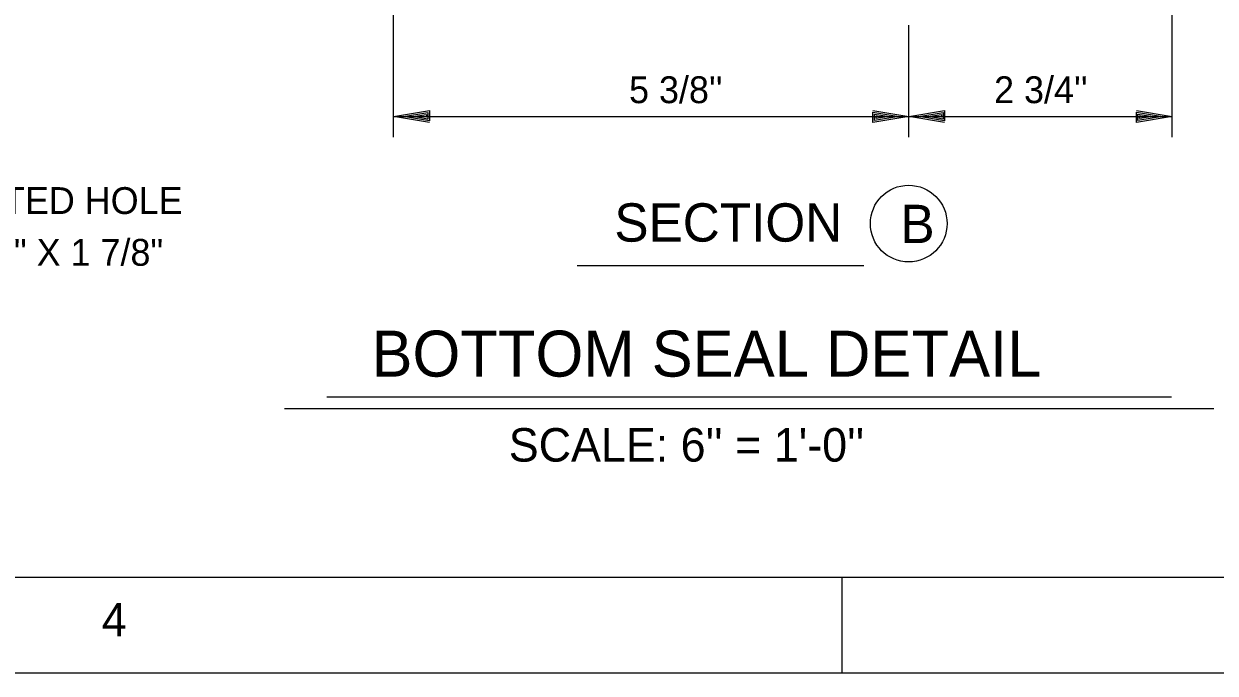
# Model space of a CAD drawing. Extents: x 0.1 to 13.5, y 0.1 to 9.5.
# Drawn here: x 4.244 to 6.316, y 0.125 to 1.255 of the extents above; entities that cross this region are included whole.
import ezdxf

# ---------------------------------------------------------------- set-up
doc = ezdxf.new("R2010")
doc.units = 0
for name, color, linetype in [('Level 1', 7, 'Continuous'), ('Level 25', 7, 'Continuous'), ('Level 3', 7, 'Continuous'), ('Level 50', 7, 'Continuous')]:
    doc.layers.add(name, color=color, linetype=linetype)

msp = doc.modelspace()

# ---------------------------------------------------------------- linework, layer by layer
at = {"layer": 'Level 1'}
msp.add_line((5.6667, 0.2917), (5.6667, 0.125), dxfattribs=at)
for points in [[(0.125, 9.4583), (13.4583, 9.4583), (13.4583, 0.125), (0.125, 0.125)], [(0.625, 9.2917), (13.2917, 9.2917), (13.2917, 0.2917), (0.625, 0.2917)]]:
    msp.add_lwpolyline(points, close=True, dxfattribs=at)
at = {"layer": 'Level 25'}
for p, q in [((4.8872, 1.0579), (4.8872, 2.0379)), ((6.2414, 1.0579), (6.2414, 1.862)), ((5.7831, 1.0579), (5.7831, 1.2525)), ((4.8872, 1.0937), (5.7831, 1.0937)), ((5.7831, 1.0937), (6.2414, 1.0937))]:
    msp.add_line(p, q, dxfattribs=at)
at = {"layer": 'Level 3'}
for p, q in [((5.7831, 1.0937), (5.7831, 1.0937)), ((5.2066, 0.8342), (5.7049, 0.8342)), ((4.7711, 0.606), (6.24, 0.606)), ((6.3138, 0.5852), (4.6973, 0.5852))]:
    msp.add_line(p, q, dxfattribs=at)
msp.add_circle((5.783, 0.9074), 0.0667, dxfattribs=at)
at = {"layer": 'Level 50'}
for p, q in [((4.8872, 1.0937), (4.8872, 1.0937)), ((4.9046, 1.0937), (4.9046, 1.0937)), ((5.7657, 1.0937), (5.7657, 1.0937)), ((5.7831, 1.0937), (5.7831, 1.0937)), ((5.7831, 1.0937), (5.7831, 1.0937)), ((5.8004, 1.0937), (5.8004, 1.0937)), ((6.2241, 1.0937), (6.2241, 1.0937)), ((6.2414, 1.0937), (6.2414, 1.0937))]:
    msp.add_line(p, q, dxfattribs=at)
for points in [[(4.9496, 1.0834), (4.8872, 1.0937), (4.9496, 1.1041), (4.9496, 1.0864), (4.9046, 1.0937), (4.9469, 1.1007), (4.9469, 1.0894), (4.9212, 1.0937), (4.9442, 1.0974), (4.9442, 1.0927), (4.9386, 1.0937)], [(5.7207, 1.1041), (5.7831, 1.0937), (5.7207, 1.0834), (5.7207, 1.1011), (5.7657, 1.0937), (5.7234, 1.0867), (5.7234, 1.0981), (5.7491, 1.0937), (5.7261, 1.0901), (5.7261, 1.0947), (5.7317, 1.0937)], [(5.8454, 1.0834), (5.7831, 1.0937), (5.8454, 1.1041), (5.8454, 1.0864), (5.8004, 1.0937), (5.8427, 1.1007), (5.8427, 1.0894), (5.8171, 1.0937), (5.8401, 1.0974), (5.8401, 1.0927), (5.8344, 1.0937)], [(6.1791, 1.1041), (6.2414, 1.0937), (6.1791, 1.0834), (6.1791, 1.1011), (6.2241, 1.0937), (6.1817, 1.0867), (6.1817, 1.0981), (6.2074, 1.0937), (6.1844, 1.0901), (6.1844, 1.0947), (6.1901, 1.0937)]]:
    msp.add_lwpolyline(points, dxfattribs=at)

# ---------------------------------------------------------------- texts
at = {"layer": 'Level 1'}
msp.add_text('4', height=0.0584, dxfattribs=at).set_placement((4.3795, 0.189))
at = {"layer": 'Level 25'}
for s, height, p in [('SLOTTED HOLE', 0.046698, (4.0446, 0.9241)), ('11/16" X 1 7/8"', 0.046698, (4.0705, 0.834)), ("SCALE: 6'' = 1'-0''", 0.058292, (5.0874, 0.4932))]:
    msp.add_text(s, height=height, dxfattribs=at).set_placement(p)
at = {"layer": 'Level 3'}
for s, height, p in [("5 3/8''", 0.0467, (5.2966, 1.117)), ("2 3/4''", 0.0467, (5.9315, 1.117)), ('SECTION  ', 0.0667, (5.271, 0.876)), ('B', 0.0667, (5.7686, 0.8735)), ('BOTTOM SEAL DETAIL ', 0.08, (4.8486, 0.6411))]:
    msp.add_text(s, height=height, dxfattribs=at).set_placement(p)

doc.saveas('drawing.dxf')
